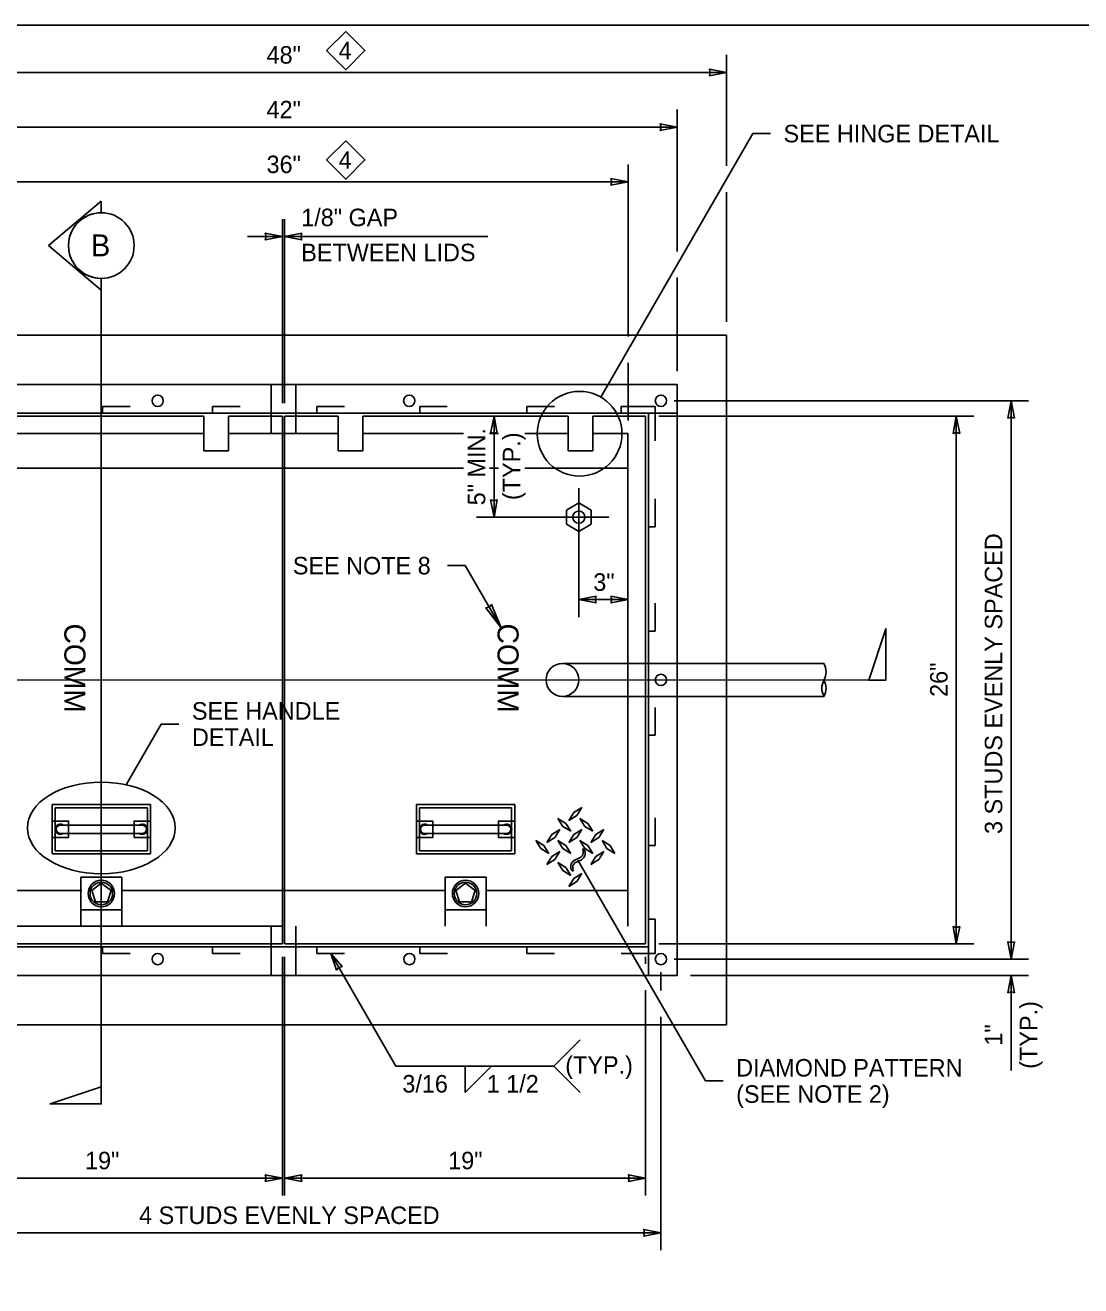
# Model space of a CAD drawing. Extents: x 99862 to 112891, y 95370 to 105076.
# Drawn here: x 100489 to 101454, y 100924 to 102076 of the extents above; entities that cross this region are included whole.
import ezdxf

# ---------------------------------------------------------------- set-up
doc = ezdxf.new("R2010")
doc.units = 0
for name, color, linetype in [('Level 1', 7, 'Continuous'), ('Level 11', 7, 'Continuous'), ('Level 13', 7, 'Continuous'), ('Level 15', 7, 'Continuous'), ('Level 2', 7, 'Continuous'), ('Level 20', 7, 'Continuous'), ('Level 3', 7, 'Continuous'), ('Level 4', 7, 'Continuous'), ('Level 5', 7, 'Continuous'), ('Level 7', 7, 'Continuous'), ('Level 8', 7, 'Continuous')]:
    doc.layers.add(name, color=color, linetype=linetype)

msp = doc.modelspace()

# ---------------------------------------------------------------- linework, layer by layer
at = {"layer": 'Level 1'}
for p, q in [((100320.4, 101792.4), (101130.4, 101792.4)), ((101130.4, 101792.4), (101130.4, 101162.4)), ((100714.2, 101702.4), (100714.2, 101747.4)), ((100736.7, 101747.4), (100736.7, 101702.4)), ((100410.7, 101671), (100889.9, 101671)), ((100913.9, 101671), (100921.9, 101671)), ((100945.9, 101671), (101040.6, 101671)), ((100410.4, 101285.2), (100541.3, 101285.2)), ((100577.8, 101285.2), (100873.3, 101285.2)), ((100910.6, 101285.2), (101040.3, 101285.2)), ((100714.2, 101252.4), (100714.2, 101207.4)), ((100736.7, 101207.4), (100736.7, 101252.4)), ((101130.4, 101162.4), (100320.4, 101162.4))]:
    msp.add_line(p, q, dxfattribs=at)
msp.add_lwpolyline([(99862, 99999.5), (103151, 99999.5), (103151, 102075.5), (99862, 102075.5)], close=True, dxfattribs=at)
at = {"layer": 'Level 11'}
for p, q in [((100577.8, 101297.3), (100540.3, 101297.3)), ((100540.3, 101297.3), (100540.3, 101267.3)), ((100577.8, 101297.3), (100577.8, 101267.3)), ((100910.6, 101297.3), (100873.1, 101297.3)), ((100873.1, 101297.3), (100873.1, 101267.3)), ((100910.6, 101297.3), (100910.6, 101267.3)), ((100577.8, 101267.3), (100540.3, 101267.3)), ((100910.6, 101267.3), (100873.1, 101267.3))]:
    msp.add_line(p, q, dxfattribs=at)
at = {"layer": 'Level 13'}
for p, q in [((100540.3, 101267.3), (100540.3, 101252.4)), ((100577.8, 101267.3), (100577.8, 101252.4)), ((100873.1, 101267.3), (100873.1, 101252.4)), ((100910.6, 101267.3), (100910.6, 101252.4))]:
    msp.add_line(p, q, dxfattribs=at)
at = {"layer": 'Level 15'}
for p, q in [((101130.4, 101946.9), (101130.4, 102048.4)), ((100320.4, 102032.4), (101130.4, 102032.4)), ((101085.4, 101868.9), (101085.4, 101998.4)), ((100365.4, 101982.4), (101085.4, 101982.4)), ((101015.5, 101735.8), (101154.5, 101976.5)), ((101154.5, 101976.5), (101170.5, 101976.5)), ((101040.4, 101791), (101040.4, 101948.4)), ((100410.4, 101932.4), (101040.4, 101932.4)), ((101130.4, 101804.4), (101130.4, 101922.9)), ((100724.5, 101730.3), (100724.5, 101898.4)), ((100726.4, 101730.3), (100726.4, 101898.4)), ((100724.5, 101882.4), (100692.5, 101882.4)), ((100726.4, 101882.4), (100912.3, 101882.4)), ((101085.4, 101759.4), (101085.4, 101844.9)), ((101040.4, 101714.4), (101040.4, 101767)), ((101082.4, 101732.4), (101406.4, 101732.4)), ((101390.4, 101732.4), (101390.4, 101222.4)), ((100917.9, 101718.3), (100917.9, 101626.1)), ((101068.4, 101718.3), (101356.4, 101718.3)), ((101340.4, 101718.3), (101340.4, 101236.4)), ((100995.4, 101652.7), (100995.4, 101534.8)), ((100901.9, 101626.1), (101022.7, 101626.1)), ((100891.5, 101581.8), (100875.5, 101581.8)), ((100924.3, 101524.9), (100891.5, 101581.8)), ((101040.4, 101550.8), (100995.4, 101550.8)), ((100581.8, 101381.6), (100613.8, 101437.1)), ((100613.8, 101437.1), (100629.8, 101437.1)), ((100991.1, 101312.5), (100994.8, 101314.2)), ((100994.8, 101314.2), (100997.1, 101315.4)), ((100997.1, 101315.4), (100998.5, 101316.6)), ((100999.9, 101315.1), (100997.9, 101313.2)), ((100998.5, 101316.6), (100999.2, 101317.8)), ((100999.5, 101320.9), (100999.1, 101323.2)), ((100999.1, 101323.2), (101000.7, 101321.9)), ((100999.2, 101317.8), (100999.5, 101319.1)), ((100999.5, 101319.1), (100999.5, 101320.9)), ((101000.8, 101316.6), (100999.9, 101315.1)), ((101000.7, 101321.9), (101001.2, 101320)), ((101001.3, 101318.2), (101000.8, 101316.6)), ((101001.2, 101320), (101001.3, 101318.2)), ((100988, 101307.8), (100988.4, 101309.3)), ((100988.1, 101306), (100988, 101307.8)), ((100988.5, 101303.9), (100988.1, 101306)), ((100988.4, 101309.3), (100989.3, 101310.8)), ((100990.2, 101302.6), (100988.5, 101303.9)), ((100989.3, 101310.8), (100991.1, 101312.5)), ((100990, 101307.9), (100989.8, 101306.3)), ((100989.8, 101306.3), (100990.2, 101302.6)), ((100990.7, 101309.1), (100990, 101307.9)), ((100991.8, 101310.2), (100990.7, 101309.1)), ((100994, 101311.3), (100991.8, 101310.2)), ((100997.9, 101313.2), (100994, 101311.3)), ((100994.6, 101312.9), (101111.2, 101111.1)), ((100544, 101252.3), (100544, 101252.5)), ((101068.4, 101236.4), (101356.4, 101236.4)), ((100724.5, 101224.4), (100724.5, 101006.4)), ((100726.4, 101224.4), (100726.4, 101006.4)), ((100768.6, 101227.6), (100828.1, 101124.5)), ((101056.4, 101224.4), (101056.4, 101218)), ((101082.4, 101222.4), (101406.4, 101222.4)), ((101097.4, 101207.4), (101406.4, 101207.4)), ((101390.4, 101207.4), (101390.4, 101120.5)), ((101056.4, 101194), (101056.4, 101006.4)), ((100972.6, 101124.5), (100996.6, 101148.5)), ((100828.1, 101124.5), (100972.6, 101124.5)), ((100891.6, 101100.5), (100915.6, 101124.5)), ((100891.6, 101124.5), (100891.6, 101100.5)), ((100972.6, 101124.5), (100996.6, 101100.5)), ((101111.2, 101111.1), (101127.2, 101111.1)), ((100724.5, 101022.4), (100394.5, 101022.4)), ((101056.4, 101022.4), (100726.4, 101022.4)), ((101070.4, 100972.4), (100380.4, 100972.4))]:
    msp.add_line(p, q, dxfattribs=at)
for points in [[(101130.4, 102032.4), (101114.7, 102029.3), (101115.5, 102032.4), (101114.7, 102035.4)], [(101085.4, 101982.4), (101069.7, 101979.3), (101070.5, 101982.4), (101069.7, 101985.4)], [(101040.4, 101932.4), (101024.7, 101929.3), (101025.5, 101932.4), (101024.7, 101935.4)], [(100724.5, 101882.4), (100708.8, 101879.3), (100709.5, 101882.4), (100708.8, 101885.4)], [(100726.4, 101882.4), (100742.1, 101879.3), (100741.4, 101882.4), (100742.1, 101885.4)], [(101390.4, 101732.4), (101387.4, 101716.6), (101390.4, 101717.4), (101393.5, 101716.6)], [(100917.9, 101718.3), (100914.8, 101702.6), (100917.9, 101703.3), (100920.9, 101702.6)], [(101340.4, 101718.3), (101337.4, 101702.6), (101340.4, 101703.3), (101343.5, 101702.6)], [(100917.9, 101626.1), (100914.8, 101641.8), (100917.9, 101641.1), (100920.9, 101641.8)], [(100924.3, 101524.9), (100910.3, 101543.2), (100913.4, 101543.8), (100915.5, 101546.2)], [(100995.4, 101550.8), (101011.2, 101547.7), (101010.4, 101550.8), (101011.2, 101553.9)], [(101040.4, 101550.8), (101024.7, 101547.7), (101025.5, 101550.8), (101024.7, 101553.9)], [(101260.5, 101477.3), (101276, 101524.2), (101276, 101477.3)], [(101340.4, 101236.4), (101337.4, 101252.1), (101340.4, 101251.4), (101343.5, 101252.1)], [(101390.4, 101222.4), (101387.4, 101238.1), (101390.4, 101237.4), (101393.5, 101238.1)], [(100768.6, 101227.6), (100773.8, 101212.4), (100776.1, 101214.6), (100779.1, 101215.5)], [(101390.4, 101207.4), (101387.4, 101191.6), (101390.4, 101192.4), (101393.5, 101191.6)], [(100724.5, 101022.4), (100708.8, 101019.3), (100709.5, 101022.4), (100708.8, 101025.4)], [(100726.4, 101022.4), (100742.1, 101019.3), (100741.4, 101022.4), (100742.1, 101025.4)], [(101056.4, 101022.4), (101040.7, 101019.3), (101041.4, 101022.4), (101040.7, 101025.4)], [(101070.4, 100972.4), (101054.7, 100969.3), (101055.5, 100972.4), (101054.7, 100975.4)]]:
    msp.add_lwpolyline(points, close=True, dxfattribs=at)
for points in [[(101070.4, 101210.4), (101070.4, 101193.6)], [(101070.4, 101169.6), (101070.4, 100956.4)]]:
    msp.add_lwpolyline(points, dxfattribs=at)
msp.add_circle((100996.1, 101702.3), 38.7, dxfattribs=at)
for centre, start, end in [((101206.4, 101484.8), 330, 30), ((101232.5, 101469.8), 150, 210), ((101206.4, 101469.8), 330, 30)]:
    msp.add_arc(centre, 15, start, end, dxfattribs=at)
msp.add_ellipse((100559, 101342.2), major_axis=(67.6, 0), ratio=0.619013, dxfattribs=at)
at = {"layer": 'Level 2'}
for p, q in [((101085.4, 101747.4), (100365.4, 101747.4)), ((101085.4, 101207.4), (101085.4, 101747.4)), ((100391.7, 101721.1), (101059.2, 101721.1)), ((101085.4, 101721.1), (101059.2, 101721.1)), ((101059.2, 101233.6), (101059.2, 101721.1)), ((100365.4, 101233.6), (101059.2, 101233.6)), ((101059.2, 101207.4), (101059.2, 101233.6)), ((101085.4, 101207.4), (100365.4, 101207.4))]:
    msp.add_line(p, q, dxfattribs=at)
at = {"layer": 'Level 20'}
for p, q in [((100559, 101914.8), (100510.6, 101874.2)), ((100559, 101904.2), (100559, 101914.8)), ((100510.6, 101874.2), (100559, 101833.6)), ((100559, 101833.6), (100559, 101844.2)), ((100559, 101844.2), (100559, 101090.1)), ((101276, 101477.3), (100192.2, 101477.4))]:
    msp.add_line(p, q, dxfattribs=at)
for points in [[(100782.4, 102069.9), (100799.9, 102052.4), (100782.4, 102034.8), (100764.8, 102052.4)], [(100782.4, 101969.9), (100799.9, 101952.4), (100782.4, 101934.8), (100764.8, 101952.4)], [(100559, 101105.7), (100512.2, 101090.1), (100559, 101090.1)]]:
    msp.add_lwpolyline(points, close=True, dxfattribs=at)
msp.add_circle((100559, 101874.2), 30, dxfattribs=at)
msp.add_arc((100559, 101874.2), 30, 89.9978, 270.0022, dxfattribs=at)
at = {"layer": 'Level 3'}
for p, q in [((100652.8, 101718.3), (100465.3, 101718.3)), ((100652.8, 101686.7), (100652.8, 101718.3)), ((100675.3, 101718.3), (100675.3, 101686.7)), ((100724.5, 101718.3), (100675.3, 101718.3)), ((100724.5, 101236.4), (100724.5, 101718.3)), ((100726.4, 101718.3), (100775.6, 101718.3)), ((100726.4, 101718.3), (100726.4, 101236.4)), ((100775.6, 101718.3), (100775.6, 101686.7)), ((100798.1, 101718.3), (100985.6, 101718.3)), ((100798.1, 101686.7), (100798.1, 101718.3)), ((100985.6, 101718.3), (100985.6, 101686.7)), ((101008.1, 101718.3), (101056.4, 101718.3)), ((101008.1, 101686.7), (101008.1, 101718.3)), ((101056.4, 101718.3), (101056.4, 101236.4)), ((100675.3, 101686.7), (100652.8, 101686.7)), ((100775.6, 101686.7), (100798.1, 101686.7)), ((100985.6, 101686.7), (101008.1, 101686.7)), ((100516.9, 101321.3), (100516.9, 101360.7)), ((100516.9, 101360.7), (100601.2, 101360.7)), ((100601.2, 101360.7), (100601.2, 101321.3)), ((100934, 101360.7), (100849.7, 101360.7)), ((100849.7, 101360.7), (100849.7, 101321.3)), ((100934, 101321.3), (100934, 101360.7)), ((100990.9, 101356.4), (100998.2, 101361)), ((100998.2, 101361), (100993.6, 101353.7)), ((100980.8, 101343.6), (100976.3, 101350.9)), ((100976.3, 101350.9), (100983.6, 101346.4)), ((100986.3, 101349.1), (100990.9, 101356.4)), ((100993.6, 101353.7), (100986.3, 101349.1)), ((101000.9, 101343.6), (100996.4, 101350.9)), ((100996.4, 101350.9), (101003.7, 101346.4)), ((100970.7, 101336.3), (100978, 101340.8)), ((100978, 101340.8), (100973.5, 101333.5)), ((100988.1, 101339.1), (100980.8, 101343.6)), ((100983.6, 101346.4), (100988.1, 101339.1)), ((100998.2, 101340.8), (100990.9, 101336.3)), ((100993.6, 101333.5), (100998.2, 101340.8)), ((101008.2, 101339.1), (101000.9, 101343.6)), ((101003.7, 101346.4), (101008.2, 101339.1)), ((101018.3, 101340.8), (101011, 101336.3)), ((101013.8, 101333.5), (101018.3, 101340.8)), ((100963.4, 101326.2), (100956.1, 101330.7)), ((100956.1, 101330.7), (100960.6, 101323.4)), ((100967.9, 101318.9), (100963.4, 101326.2)), ((100966.2, 101329), (100970.7, 101336.3)), ((100973.5, 101333.5), (100966.2, 101329)), ((100983.6, 101326.2), (100976.3, 101330.7)), ((100976.3, 101330.7), (100980.8, 101323.4)), ((100988.1, 101318.9), (100983.6, 101326.2)), ((100990.9, 101336.3), (100986.4, 101329)), ((100986.4, 101329), (100993.6, 101333.5)), ((101000.9, 101323.4), (100996.4, 101330.7)), ((100996.4, 101330.7), (101003.7, 101326.2)), ((101003.7, 101326.2), (101008.2, 101318.9)), ((101011, 101336.3), (101006.5, 101329)), ((101006.5, 101329), (101013.8, 101333.5)), ((101021.1, 101323.4), (101016.6, 101330.7)), ((101016.6, 101330.7), (101023.9, 101326.2)), ((101023.9, 101326.2), (101028.4, 101318.9)), ((100601.2, 101321.3), (100516.9, 101321.3)), ((100849.7, 101321.3), (100934, 101321.3)), ((100960.6, 101323.4), (100967.9, 101318.9)), ((100970.7, 101316.1), (100966.2, 101308.8)), ((100978, 101320.6), (100970.7, 101316.1)), ((100973.5, 101313.3), (100978, 101320.6)), ((100980.8, 101323.4), (100988.1, 101318.9)), ((101008.2, 101318.9), (101000.9, 101323.4)), ((101011, 101316.1), (101006.5, 101308.8)), ((101018.3, 101320.6), (101011, 101316.1)), ((101013.8, 101313.3), (101018.3, 101320.6)), ((101028.4, 101318.9), (101021.1, 101323.4)), ((100966.2, 101308.8), (100973.5, 101313.3)), ((100980.8, 101303.3), (100976.3, 101310.6)), ((100976.3, 101310.6), (100983.6, 101306)), ((100988.1, 101298.7), (100980.8, 101303.3)), ((100983.6, 101306), (100988.1, 101298.7)), ((101006.5, 101308.8), (101013.8, 101313.3)), ((100990.9, 101296), (100986.3, 101288.7)), ((100986.3, 101288.7), (100993.6, 101293.2)), ((100998.2, 101300.5), (100990.9, 101296)), ((100993.6, 101293.2), (100998.2, 101300.5)), ((100394.5, 101236.4), (100724.5, 101236.4)), ((101056.4, 101236.4), (100726.4, 101236.4))]:
    msp.add_line(p, q, dxfattribs=at)
for centre in [(100559, 101282.3), (100891.9, 101282.3)]:
    msp.add_circle(centre, 12.1, dxfattribs=at)
at = {"layer": 'Level 4'}
for p, q in [((100984.2, 101632.6), (100995.4, 101639.1)), ((100995.4, 101639.1), (101006.7, 101632.6)), ((100984.2, 101619.6), (100984.2, 101632.6)), ((101006.7, 101632.6), (101006.7, 101619.6)), ((100995.4, 101613.1), (100984.2, 101619.6)), ((101006.7, 101619.6), (100995.4, 101613.1)), ((100514, 101363.5), (100604, 101363.5)), ((100514, 101318.5), (100514, 101363.5)), ((100604, 101363.5), (100604, 101318.5)), ((100846.9, 101363.5), (100936.9, 101363.5)), ((100846.9, 101318.5), (100846.9, 101363.5)), ((100936.9, 101363.5), (100936.9, 101318.5)), ((100521.5, 101344.7), (100529, 101344.7)), ((100529, 101337.2), (100521.5, 101337.2)), ((100589, 101344.7), (100529, 101344.7)), ((100529, 101337.2), (100589, 101337.2)), ((100589, 101344.7), (100596.5, 101344.7)), ((100596.5, 101337.2), (100589, 101337.2)), ((100854.4, 101344.7), (100861.9, 101344.7)), ((100861.9, 101337.2), (100854.4, 101337.2)), ((100921.9, 101344.7), (100861.9, 101344.7)), ((100861.9, 101337.2), (100921.9, 101337.2)), ((100921.9, 101344.7), (100929.4, 101344.7)), ((100929.4, 101337.2), (100921.9, 101337.2)), ((100589, 101333.5), (100604, 101333.5)), ((100604, 101318.5), (100514, 101318.5)), ((100936.9, 101318.5), (100846.9, 101318.5))]:
    msp.add_line(p, q, dxfattribs=at)
for points in [[(100514, 101333.5), (100529, 101333.5), (100529, 101348.5), (100514, 101348.5)], [(100604, 101348.5), (100604, 101348.5), (100589, 101348.5), (100589, 101333.5)], [(100846.9, 101333.5), (100861.9, 101333.5), (100861.9, 101348.5), (100846.9, 101348.5)], [(100936.9, 101333.5), (100921.9, 101333.5), (100921.9, 101348.5), (100936.9, 101348.5)]]:
    msp.add_lwpolyline(points, dxfattribs=at)
msp.add_circle((100995.4, 101626.1), 5.62, dxfattribs=at)
for centre, radius, start, end in [((100521.5, 101341), 4.69, 53.1301, 306.8699), ((100521.5, 101341), 3.75, 90, 270), ((100596.5, 101341), 4.69, 0, 126.8699), ((100596.5, 101341), 4.69, 233.1301, 0), ((100596.5, 101341), 3.75, 270, 90), ((100854.4, 101341), 4.69, 53.1301, 306.8699), ((100854.4, 101341), 3.75, 90, 270), ((100929.4, 101341), 4.69, 0, 126.8699), ((100929.4, 101341), 4.69, 233.1301, 0), ((100929.4, 101341), 3.75, 270, 90)]:
    msp.add_arc(centre, radius, start, end, dxfattribs=at)
at = {"layer": 'Level 5'}
for centre, start, end in [((100610.5, 101732.4), 0, 180), ((100610.5, 101732.4), 180, 0), ((100840.4, 101732.4), 0, 180), ((100840.4, 101732.4), 180, 0), ((101070.4, 101732.4), 0, 180), ((101070.4, 101732.4), 180, 0), ((101070.4, 101477.4), 0, 180), ((101070.4, 101477.4), 180, 0), ((100610.5, 101222.4), 0, 180), ((100610.5, 101222.4), 180, 0), ((100840.5, 101222.4), 0, 180), ((100840.5, 101222.4), 180, 0), ((101070.4, 101222.4), 0, 180), ((101070.4, 101222.4), 180, 0)]:
    msp.add_arc(centre, 5.16, start, end, dxfattribs=at)
at = {"layer": 'Level 7'}
for p, q in [((100559, 101291.6), (100550.2, 101285.2)), ((100567.9, 101285.2), (100559, 101291.6)), ((100891.9, 101291.6), (100883, 101285.2)), ((100900.7, 101285.2), (100891.9, 101291.6)), ((100550.2, 101285.2), (100553.6, 101274.8)), ((100564.5, 101274.8), (100567.9, 101285.2)), ((100883, 101285.2), (100886.4, 101274.8)), ((100897.3, 101274.8), (100900.7, 101285.2)), ((100553.6, 101274.8), (100564.5, 101274.8)), ((100886.4, 101274.8), (100897.3, 101274.8))]:
    msp.add_line(p, q, dxfattribs=at)
for centre in [(100559, 101282.3), (100891.9, 101282.3)]:
    msp.add_circle(centre, 10.3, dxfattribs=at)
at = {"layer": 'Level 8'}
for p, q in [((100560.1, 101727.1), (100585.3, 101727.1)), ((100560.1, 101721.1), (100560.1, 101727.1)), ((100585.3, 101721.1), (100560.1, 101721.1)), ((100660.7, 101727.1), (100685.9, 101727.1)), ((100660.7, 101721.1), (100660.7, 101727.1)), ((100685.9, 101721.1), (100660.7, 101721.1)), ((100756, 101727.1), (100781.2, 101727.1)), ((100756, 101721.1), (100756, 101727.1)), ((100781.2, 101721.1), (100756, 101721.1)), ((100850, 101727.1), (100875.2, 101727.1)), ((100850, 101721.1), (100850, 101727.1)), ((100875.2, 101721.1), (100850, 101721.1)), ((100948, 101727.1), (100973.2, 101727.1)), ((100948, 101721.1), (100948, 101727.1)), ((100973.2, 101721.1), (100948, 101721.1)), ((101034, 101727.1), (101065.2, 101727.1)), ((101034, 101721.1), (101034, 101727.1)), ((101059.2, 101721.1), (101034, 101721.1)), ((101059.2, 101695.9), (101059.2, 101721.1)), ((101065.2, 101727.1), (101065.2, 101695.9)), ((100465.3, 101702.4), (100652.8, 101702.4)), ((100675.3, 101702.4), (100775.6, 101702.4)), ((100798.1, 101702.4), (100889.9, 101702.4)), ((100913.9, 101702.4), (100921.9, 101702.4)), ((100945.9, 101702.4), (100985.6, 101702.4)), ((101040.4, 101702.4), (101008.1, 101702.4)), ((101040.3, 101252.4), (101040.3, 101702.4)), ((101059.2, 101642.7), (101059.2, 101617.4)), ((101065.2, 101617.4), (101065.2, 101642.7)), ((101059.2, 101617.4), (101065.2, 101617.4)), ((101059.2, 101547.4), (101059.2, 101522.1)), ((101065.2, 101522.1), (101065.2, 101547.4)), ((101059.2, 101522.1), (101065.2, 101522.1)), ((101130.4, 101492.4), (100980.4, 101492.4)), ((101219.5, 101492.4), (101130.4, 101492.4)), ((101219.5, 101492.4), (101219.5, 101492.4)), ((100980.4, 101462.4), (101130.4, 101462.4)), ((101059.2, 101452.1), (101059.2, 101426.9)), ((101065.2, 101426.9), (101065.2, 101452.1)), ((101130.4, 101462.4), (101219.5, 101462.4)), ((101059.2, 101426.9), (101065.2, 101426.9)), ((101059.2, 101351.5), (101059.2, 101326.3)), ((101065.2, 101326.3), (101065.2, 101351.5)), ((101059.2, 101326.3), (101065.2, 101326.3)), ((101059.2, 101233.6), (101059.2, 101258.8)), ((101059.2, 101258.8), (101065.2, 101258.8)), ((101065.2, 101258.8), (101065.2, 101227.6)), ((100410.5, 101252.4), (100724.5, 101252.4)), ((100560.1, 101233.6), (100585.4, 101233.6)), ((100560.1, 101227.6), (100560.1, 101233.6)), ((100660.7, 101233.6), (100685.9, 101233.6)), ((100660.7, 101227.6), (100660.7, 101233.6)), ((100756, 101233.6), (100781.2, 101233.6)), ((100756, 101227.6), (100756, 101233.6)), ((100850, 101233.6), (100875.3, 101233.6)), ((100850, 101227.6), (100850, 101233.6)), ((100948, 101233.6), (100973.2, 101233.6)), ((100948, 101227.6), (100948, 101233.6)), ((101034, 101233.6), (101059.2, 101233.6)), ((100585.4, 101227.6), (100560.1, 101227.6)), ((100685.9, 101227.6), (100660.7, 101227.6)), ((100781.2, 101227.6), (100756, 101227.6)), ((100875.3, 101227.6), (100850, 101227.6)), ((100973.2, 101227.6), (100948, 101227.6)), ((101065.2, 101227.6), (101034, 101227.6))]:
    msp.add_line(p, q, dxfattribs=at)
msp.add_circle((100980.4, 101477.4), 15, dxfattribs=at)

# ---------------------------------------------------------------- texts
at = {"layer": 'Level 15'}
for s, p in [('5" MIN.', (100909.9, 101636.9)), ('(TYP.)', (100941.9, 101641.7))]:
    msp.add_text(s, height=16, rotation=90, dxfattribs=at).set_placement(p)
at = {"layer": 'Level 20'}
for s, height, p in [('48"', 16, (100710, 102040.4)), ('42"', 16, (100710, 101990.4)), ('SEE HINGE DETAIL', 16, (101182.5, 101968.5)), ('36"', 16, (100710, 101940.4)), ('B', 20, (100549.4, 101864.4)), ('SEE HANDLE', 16, (100641.8, 101441.1)), ('DETAIL', 16, (100641.8, 101417.1)), ('(TYP.)', 16, (100983, 101117.6)), ('DIAMOND PATTERN', 16, (101139.2, 101115.1)), ('3/16', 16, (100834.1, 101100.5)), ('1 1/2', 16, (100911.2, 101100.5)), ('(SEE NOTE 2)', 16, (101139.2, 101091.1)), ('19"', 16, (100544.1, 101030.4)), ('19"', 16, (100876, 101030.4)), ('4 STUDS EVENLY SPACED', 16, (100593.5, 100980.4))]:
    msp.add_text(s, height=height, dxfattribs=at).set_placement(p)
for s, height, rotation, p in [('4', 16, 360, (100775.9, 102044.4)), ('4', 16, 360, (100775.9, 101944.4)), ('1/8" GAP', 16, 360, (100741.7, 101891.9)), ('BETWEEN LIDS', 16, 360, (100741.7, 101859.9)), ('3 STUDS EVENLY SPACED', 16, 90, (101382.4, 101336.7)), ('SEE NOTE 8', 16, 360, (100734, 101573.8)), ('3"', 16, 360, (101008.6, 101558.8)), ('COMM', 19.25, 270, (100525.2, 101528.9)), ('COMM', 19.25, 270, (100921.1, 101528.9)), ('26"', 16, 90, (101332.4, 101461.9)), ('(TYP.)', 16, 90, (101414.4, 101122.2)), ('1"', 16, 90, (101382.4, 101143.3))]:
    msp.add_text(s, height=height, rotation=rotation, dxfattribs=at).set_placement(p)

doc.saveas('drawing.dxf')
